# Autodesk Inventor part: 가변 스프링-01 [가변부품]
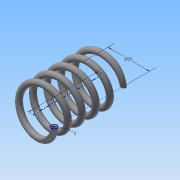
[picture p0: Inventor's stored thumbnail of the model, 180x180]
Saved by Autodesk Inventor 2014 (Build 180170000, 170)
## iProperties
Created: 2015-09
Part Number: 가변 스프링-01 [가변부품]
Material: 강철, 탄소
Document SubType Name: Modeling
Designer: study
Density: 7.87 g/cm^3
Appearance: 반연마
Mass: 18.8111 g
Surface Area: 32.4633 cm^2
Volume: 2.39023 cm^3
Author: study
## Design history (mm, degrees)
sketch "스케치1"
  geometry: L1 (0, 0)-(11, 0); L2 (11, 0)-(11, 28.893); L3 (11, 28.893)-(0, 28.893); L4 (0, 28.893)-(0, 0); C1 r 1.5 at (11, 0)
  constraints: 8 end point, 2 parallel, 1 centre point, 1 coincident, 1 horizontal, 1 perpendicular
  dimensions: "d0" = 22 diameter of L2.end L4; "d1" = 3 diameter of C1; "d2" = 28.89259 distance of L3.end L1.start (derived)
feature "코일1" sketch "스케치1" pitch "d3" = 10; turns "d5" = 5; dims "d4" = 28.89259 (= d2), "d6" = 0, angle "d7" = 90 deg, angle "d8" = 90 deg, "d9" = 0, "d10" = 0
node "작업 평면1"
sketch "스케치2"
  geometry: L1 (-12.5, 0)-(-9.5, 0) reference; 1 further point
  constraints: 1 horizontal alignment
extrude "돌출1" cut sketch "스케치2" stored distance "d12" = 10; taper "d13" = 0 deg
node "작업 평면2"
sketch "스케치3"
  geometry: L1 (-9.5, 0)-(-12.5, 0) reference; 1 further point
  constraints: 1 horizontal alignment
extrude "돌출2" cut sketch "스케치3" distance "d15" = 10; taper "d16" = 0 deg
node "솔리드1"
node "절단 모서리 투영1"
node "절단 모서리 투영2"
other parameters: "d11" = 0, "d14" = 28.89259 (= d2)
